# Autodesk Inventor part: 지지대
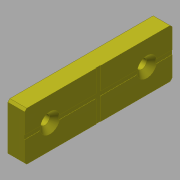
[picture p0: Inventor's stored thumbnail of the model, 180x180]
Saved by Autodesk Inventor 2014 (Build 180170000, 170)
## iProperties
Created: 2017-04
Part Number: 지지대
Material: 강철
Document SubType Name: Modeling
Designer: mduedu
Density: 7.85 g/cm^3
Appearance: 밝은 황색
Mass: 97.8484 g
Surface Area: 48.4895 cm^2
Volume: 12.4648 cm^3
Author: mduedu
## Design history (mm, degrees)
sketch "스케치1"
  geometry: L1 (23, -35)-(23, 35); L2 (0, -35)-(0, 35); L3 (0, 35)-(23, 35); L4 (0, -35)-(23, -35); 2 further points
  constraints: 8 end point, 2 parallel, 1 coincident, 1 midpoint, 1 perpendicular, 1 vertical
  dimensions: "d1" = 23 distance between parallel lines of L2 L1; "d15" = 70 distance of L1.start L1.end
extrude "돌출1" new body sketch "스케치1" distance "d2" = 8; taper "d3" = 0 deg
chamfer "모따기2" distance "d16" = 1; stored, may be unused: second distance "d17" = 2, angle "d18" = 45 deg
sketch "스케치2"
  geometry: L1 (1, -35)-(22, -35) reference; L2 (23, -34)-(23, 34) reference; L3 (22, 35)-(1, 35) reference; L4 (0, 34)-(0, -34) reference; L5 (11.5, 35)-(11.5, -35); L6 (23, 0)-(0, 0); L7 (1, -35)-(0, -34) reference; L8 (23, -34)-(22, -35) reference; L9 (22, 35)-(23, 34) reference; L10 (0, 34)-(1, 35) reference; 2 further points
  constraints: 4 end point, 4 midpoint, 1 point on line, 1 symmetric about line
  dimensions: "d7" = 12 distance from line of point (11.5, 23) L3
  node "투영된 루프1"
sketch "스케치3"
  geometry: 4 further points
  constraints: 2 coincident
hole "구멍1" sketch "스케치3" at (11.5, 23), (11.5, -23) diameter "d8" = 4.5; stored, may be unused: countersink angle "d12" = 90 deg, drill point angle "d14" = 0 deg; dims "d9" = 6, "d10" = 9.4, "d11" = 2, "d13" = 8
sketch "스케치4"
  geometry: L1 (-35, 22)-(-35, 1) reference; L2 (35, 1)-(35, 22) reference; L3 (34, 23)-(-34, 23) reference; L4 (-34, 0)-(34, 0) reference; L5 (-35, 11.5)-(35, 11.5); L6 (0, 23)-(0, 0); L7 (-35, 12.5)-(35, 12.5); L8 (-35, 10.5)-(35, 10.5); L9 (-1, 23)-(-1, 0); L10 (1, 23)-(1, 0)
  constraints: 12 end point, 8 point on line, 4 parallel, 3 midpoint, 3 perpendicular
  dimensions: "d19" = 1 distance between parallel lines of L7 L5; "d21" = 1 distance between parallel lines of L8 L5; "d22" = 1 distance between parallel lines of L9 L6; "d23" = 1 distance between parallel lines of L10 L6
extrude "돌출2" cut sketch "스케치4" distance "d24" = 0.2; taper "d25" = 0 deg
extrude "돌출3" cut sketch "스케치4" distance "d26" = 0.2; taper "d27" = 0 deg
fillet "모깎기1" dims "d28" = 0.2
node "솔리드2"
node "솔리드1"
